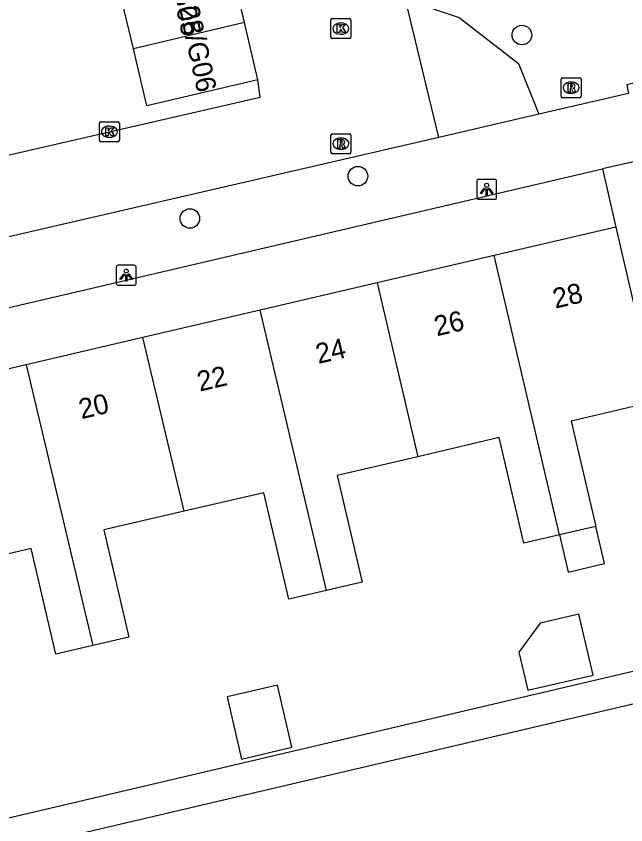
# Model space of a CAD drawing. Extents: x 158038 to 159242, y 380133 to 381214.
# Drawn here: x 158654.81 to 158685.28, y 380891.42 to 380931.84 of the extents above; entities that cross this region are included whole.
import ezdxf

# ---------------------------------------------------------------- set-up
doc = ezdxf.new("R2010")
doc.units = 0
for name, color, linetype in [('IMGEO_Boom', 7, 'Continuous'), ('IMGEO_Groenvoorziening', 7, 'Continuous'), ('IMGEO_Kolk', 7, 'Continuous'), ('IMGEO_Lichtpunt', 7, 'Continuous'), ('IMGEO_Pand', 7, 'Continuous'), ('IMGEO_Pand_nummerreeks', 7, 'Continuous'), ('IMGEO_Rijbaan_lokaal_open', 7, 'Continuous'), ('IMGEO_Rioolput', 7, 'Continuous'), ('IMGEO_Voetpad_open', 7, 'Continuous')]:
    doc.layers.add(name, color=color, linetype=linetype)

msp = doc.modelspace()

# ---------------------------------------------------------------- linework, layer by layer
at = {"layer": 'IMGEO_Boom'}
for centre in [(158680.085, 380930.895), (158671.888, 380923.84), (158663.489, 380921.724)]:
    msp.add_circle(centre, 0.489, dxfattribs=at)
at = {"layer": 'IMGEO_Groenvoorziening'}
for points in [[(158674.266, 380932.695), (158676.956, 380931.767), (158679.919, 380929.472), (158680.934, 380926.931)], [(158684.109, 380924.199), (158684.772, 380921.288)]]:
    msp.add_lwpolyline(points, dxfattribs=at)
at = {"layer": 'IMGEO_Kolk'}
for p, q in [((158670.533, 380930.79), (158670.533, 380931.642)), ((158670.608, 380931.716), (158671.46, 380931.716)), ((158671.021, 380931.496), (158671.046, 380931.496)), ((158671.534, 380931.642), (158671.534, 380930.79)), ((158671.46, 380930.716), (158670.608, 380930.716)), ((158671.044, 380930.936), (158671.019, 380930.936)), ((158659.041, 380926.561), (158659.893, 380926.561)), ((158658.966, 380925.635), (158658.966, 380926.487)), ((158659.454, 380926.341), (158659.479, 380926.341)), ((158659.967, 380926.487), (158659.967, 380925.635)), ((158659.477, 380925.781), (158659.452, 380925.781)), ((158659.893, 380925.561), (158659.041, 380925.561))]:
    msp.add_line(p, q, dxfattribs=at)
for points in [[(158670.533, 380930.79), (158670.533, 380931.642)], [(158670.608, 380931.716), (158671.46, 380931.716)], [(158670.854, 380931.416), (158670.977, 380931.416), (158670.977, 380931.265), (158671.107, 380931.416), (158671.271, 380931.416), (158671.125, 380931.265), (158671.278, 380931.016), (158671.126, 380931.016), (158671.041, 380931.18), (158670.977, 380931.113), (158670.977, 380931.016), (158670.854, 380931.016), (158670.854, 380931.416)], [(158671.534, 380931.642), (158671.534, 380930.79)], [(158671.46, 380930.716), (158670.608, 380930.716)], [(158659.041, 380926.561), (158659.893, 380926.561)], [(158658.966, 380925.635), (158658.966, 380926.487)], [(158659.287, 380926.261), (158659.41, 380926.261), (158659.41, 380926.11), (158659.54, 380926.261), (158659.704, 380926.261), (158659.558, 380926.11), (158659.711, 380925.861), (158659.559, 380925.861), (158659.474, 380926.025), (158659.41, 380925.958), (158659.41, 380925.861), (158659.287, 380925.861), (158659.287, 380926.261)], [(158659.967, 380926.487), (158659.967, 380925.635)], [(158659.893, 380925.561), (158659.041, 380925.561)]]:
    msp.add_lwpolyline(points, dxfattribs=at)
for centre, start, end in [((158670.61, 380931.64), 91.552, 178.448), ((158670.61, 380931.64), 91.552, 178.448), ((158671.458, 380931.64), 1.552, 88.448), ((158671.458, 380931.64), 1.552, 88.448), ((158670.61, 380930.792), 181.552, 268.448), ((158670.61, 380930.792), 181.552, 268.448), ((158671.458, 380930.792), 271.552, 358.448), ((158671.458, 380930.792), 271.552, 358.448), ((158659.043, 380926.485), 91.552, 178.448), ((158659.043, 380926.485), 91.552, 178.448), ((158659.891, 380926.485), 1.552, 88.448), ((158659.891, 380926.485), 1.552, 88.448), ((158659.043, 380925.637), 181.552, 268.448), ((158659.043, 380925.637), 181.552, 268.448), ((158659.891, 380925.637), 271.552, 358.448), ((158659.891, 380925.637), 271.552, 358.448)]:
    msp.add_arc(centre, 0.0765, start, end, dxfattribs=at)
for centre, major_axis, ratio, start_param, end_param in [((158671.02, 380931.216), (-0.387, 0.002), 0.722429, 4.712389, 7.853982), ((158671.045, 380931.216), (-0.39, 0.002), 0.717154, 1.570796, 4.712389), ((158659.453, 380926.061), (-0.387, 0.002), 0.722429, 4.712389, 7.853982), ((158659.478, 380926.061), (-0.39, 0.002), 0.717154, 1.570796, 4.712389)]:
    msp.add_ellipse(centre, major_axis=major_axis, ratio=ratio, start_param=start_param, end_param=end_param, dxfattribs=at)
at = {"layer": 'IMGEO_Lichtpunt'}
for p, q in [((158677.826, 380923.585), (158677.826, 380922.778)), ((158677.826, 380923.585), (158677.826, 380922.778)), ((158678.728, 380923.68), (158677.92, 380923.68)), ((158678.728, 380923.68), (158677.92, 380923.68)), ((158678.822, 380922.778), (158678.822, 380923.585)), ((158678.822, 380922.778), (158678.822, 380923.585)), ((158677.92, 380922.684), (158678.728, 380922.684)), ((158677.92, 380922.684), (158678.728, 380922.684)), ((158659.808, 380919.295), (158659.808, 380918.488)), ((158659.808, 380919.295), (158659.808, 380918.488)), ((158660.71, 380919.39), (158659.902, 380919.39)), ((158660.71, 380919.39), (158659.902, 380919.39)), ((158660.804, 380918.488), (158660.804, 380919.295)), ((158660.804, 380918.488), (158660.804, 380919.295)), ((158659.902, 380918.394), (158660.71, 380918.394)), ((158659.902, 380918.394), (158660.71, 380918.394))]:
    msp.add_line(p, q, dxfattribs=at)
for points in [[(158678.2, 380923.249), (158678.239, 380923.221), (158678.051, 380922.959), (158678.013, 380922.986), (158678.2, 380923.249)], [(158678.302, 380923.201), (158678.349, 380923.201), (158678.349, 380922.879), (158678.302, 380922.879), (158678.302, 380923.201)], [(158678.412, 380923.221), (158678.45, 380923.248), (158678.637, 380922.986), (158678.598, 380922.958), (158678.412, 380923.221)], [(158660.182, 380918.959), (158660.221, 380918.931), (158660.033, 380918.669), (158659.995, 380918.696), (158660.182, 380918.959)], [(158660.284, 380918.911), (158660.331, 380918.911), (158660.331, 380918.589), (158660.284, 380918.589), (158660.284, 380918.911)], [(158660.394, 380918.931), (158660.432, 380918.958), (158660.619, 380918.696), (158660.58, 380918.668), (158660.394, 380918.931)]]:
    msp.add_lwpolyline(points, dxfattribs=at)
for centre in [(158678.325, 380923.383), (158660.307, 380919.093)]:
    msp.add_circle(centre, 0.0994, dxfattribs=at)
for centre, start, end in [((158677.92, 380923.585), 90, 180), ((158677.92, 380923.585), 90, 180), ((158678.728, 380923.585), 0, 90), ((158678.728, 380923.585), 0, 90), ((158677.92, 380922.778), 180, 270), ((158677.92, 380922.778), 180, 270), ((158678.728, 380922.778), 270, 0), ((158678.728, 380922.778), 270, 360), ((158659.902, 380919.295), 90, 180), ((158659.902, 380919.295), 90, 180), ((158660.71, 380919.295), 0, 90), ((158660.71, 380919.295), 0, 90), ((158659.902, 380918.488), 180, 270), ((158659.902, 380918.488), 180, 270), ((158660.71, 380918.488), 270, 0), ((158660.71, 380918.488), 270, 360)]:
    msp.add_arc(centre, 0.0946, start, end, dxfattribs=at)
at = {"layer": 'IMGEO_Pand'}
for points in [[(158666.218, 380931.513), (158665.546, 380934.366)], [(158660.663, 380930.206), (158659.991, 380933.058)], [(158666.218, 380931.513), (158660.663, 380930.206)], [(158666.889, 380928.661), (158666.218, 380931.513)], [(158666.889, 380928.661), (158661.334, 380927.354), (158660.663, 380930.206)], [(158684.772, 380921.288), (158678.701, 380919.872)], [(158684.772, 380921.288), (158686.8, 380912.592)], [(158678.701, 380919.872), (158672.845, 380918.506)], [(158681.969, 380905.911), (158678.701, 380919.872)], [(158672.845, 380918.506), (158667, 380917.143)], [(158672.845, 380918.506), (158674.882, 380909.821)], [(158667, 380917.143), (158661.145, 380915.777)], [(158670.312, 380903.139), (158667, 380917.143)], [(158661.145, 380915.777), (158655.3, 380914.414)], [(158663.205, 380907.093), (158661.145, 380915.777)], [(158655.3, 380914.414), (158649.241, 380913.001)], [(158655.3, 380914.414), (158658.634, 380900.384)], [(158686.8, 380912.592), (158682.546, 380911.6), (158683.775, 380906.332)], [(158681.969, 380905.911), (158680.186, 380905.495), (158678.956, 380910.771), (158674.882, 380909.821)], [(158674.882, 380909.821), (158670.853, 380908.882), (158672.095, 380903.555), (158670.312, 380903.139)], [(158670.312, 380903.139), (158668.431, 380902.7), (158667.19, 380908.022), (158663.205, 380907.093)], [(158663.205, 380907.093), (158659.196, 380906.158), (158660.444, 380900.806), (158658.634, 380900.384)], [(158683.775, 380906.332), (158681.969, 380905.911)], [(158681.969, 380905.911), (158682.403, 380904.056), (158684.208, 380904.477), (158683.775, 380906.332)], [(158658.634, 380900.384), (158656.788, 380899.953), (158655.558, 380905.23), (158651.286, 380904.234)], [(158679.938, 380900.042), (158680.38, 380898.148), (158683.639, 380898.909), (158682.929, 380901.95), (158680.996, 380901.499), (158679.938, 380900.042)], [(158665.347, 380897.819), (158666.072, 380894.709), (158668.59, 380895.297), (158667.865, 380898.406), (158665.347, 380897.819)]]:
    msp.add_lwpolyline(points, dxfattribs=at)
at = {"layer": 'IMGEO_Rijbaan_lokaal_open'}
for points in [[(158675.929, 380925.769), (158674.266, 380932.695)], [(158638.865, 380921.332), (158667.001, 380927.792), (158666.889, 380928.661)], [(158675.929, 380925.769), (158636.891, 380916.763), (158636.843, 380917.154), (158619.873, 380913.305), (158620.128, 380912.212), (158625.512, 380888.677), (158633.627, 380853.786), (158633.666, 380853.62)]]:
    msp.add_lwpolyline(points, dxfattribs=at)
at = {"layer": 'IMGEO_Rioolput'}
for p, q in [((158682.045, 380927.836), (158682.045, 380928.688)), ((158682.12, 380928.762), (158682.972, 380928.762)), ((158683.046, 380928.688), (158683.046, 380927.836)), ((158682.533, 380928.542), (158682.558, 380928.542)), ((158682.972, 380927.762), (158682.12, 380927.762)), ((158682.556, 380927.982), (158682.531, 380927.982)), ((158670.537, 380925.038), (158670.537, 380925.89)), ((158670.612, 380925.964), (158671.464, 380925.964)), ((158671.025, 380925.744), (158671.05, 380925.744)), ((158671.538, 380925.89), (158671.538, 380925.038)), ((158671.464, 380924.964), (158670.612, 380924.964)), ((158671.048, 380925.184), (158671.023, 380925.184))]:
    msp.add_line(p, q, dxfattribs=at)
for points in [[(158682.045, 380927.836), (158682.045, 380928.688)], [(158682.12, 380928.762), (158682.972, 380928.762)], [(158683.046, 380928.688), (158683.046, 380927.836)], [(158682.634, 380928.46), (158682.382, 380928.462), (158682.382, 380928.062)], [(158682.382, 380928.062), (158682.506, 380928.062), (158682.506, 380928.224), (158682.517, 380928.224)], [(158682.56, 380928.381), (158682.506, 380928.381), (158682.506, 380928.3)], [(158682.506, 380928.3), (158682.558, 380928.3)], [(158682.564, 380928.195), (158682.635, 380928.062), (158682.775, 380928.062), (158682.71, 380928.188)], [(158682.972, 380927.762), (158682.12, 380927.762)], [(158670.537, 380925.038), (158670.537, 380925.89)], [(158670.612, 380925.964), (158671.464, 380925.964)], [(158671.538, 380925.89), (158671.538, 380925.038)], [(158671.126, 380925.662), (158670.874, 380925.664), (158670.874, 380925.264)], [(158670.874, 380925.264), (158670.998, 380925.264), (158670.998, 380925.426), (158671.009, 380925.426)], [(158671.052, 380925.583), (158670.998, 380925.583), (158670.998, 380925.502)], [(158670.998, 380925.502), (158671.05, 380925.502)], [(158671.056, 380925.397), (158671.127, 380925.264), (158671.267, 380925.264), (158671.202, 380925.39)], [(158671.464, 380924.964), (158670.612, 380924.964)]]:
    msp.add_lwpolyline(points, dxfattribs=at)
for centre, radius, start, end in [((158682.122, 380928.686), 0.0765, 91.552, 178.448), ((158682.122, 380928.686), 0.0765, 91.552, 178.448), ((158682.97, 380928.686), 0.0765, 1.552, 88.448), ((158682.97, 380928.686), 0.0765, 1.552, 88.448), ((158682.516, 380928.171), 0.0533, 26.0293, 88.6989), ((158682.542, 380928.489), 0.19, 274.7715, 282.9687), ((158682.566, 380928.285), 0.0964, 77.0061, 93.1865), ((158682.58, 380928.342), 0.0378, 276.6634, 79.6772), ((158682.633, 380928.35), 0.109, 350.3612, 89.416), ((158682.631, 380928.35), 0.112, 277.5842, 350.9817), ((158682.615, 380928.135), 0.108, 29.5134, 73.7905), ((158682.122, 380927.838), 0.0765, 181.552, 268.448), ((158682.122, 380927.838), 0.0765, 181.552, 268.448), ((158682.97, 380927.838), 0.0765, 271.552, 358.448), ((158682.97, 380927.838), 0.0765, 271.552, 358.448), ((158670.614, 380925.888), 0.0765, 91.552, 178.448), ((158670.614, 380925.888), 0.0765, 91.552, 178.448), ((158671.462, 380925.888), 0.0765, 1.552, 88.448), ((158671.462, 380925.888), 0.0765, 1.552, 88.448), ((158671.008, 380925.373), 0.0533, 26.0293, 88.6989), ((158671.034, 380925.691), 0.19, 274.7715, 282.9687), ((158671.058, 380925.487), 0.0964, 77.0061, 93.1865), ((158671.072, 380925.544), 0.0378, 276.6634, 79.6772), ((158671.125, 380925.552), 0.109, 350.3612, 89.416), ((158671.123, 380925.552), 0.112, 277.5842, 350.9817), ((158671.107, 380925.337), 0.108, 29.5134, 73.7905), ((158670.614, 380925.04), 0.0765, 181.552, 268.448), ((158670.614, 380925.04), 0.0765, 181.552, 268.448), ((158671.462, 380925.04), 0.0765, 271.552, 358.448), ((158671.462, 380925.04), 0.0765, 271.552, 358.448)]:
    msp.add_arc(centre, radius, start, end, dxfattribs=at)
for centre, major_axis, ratio, start_param, end_param in [((158682.532, 380928.262), (-0.387, 0.002), 0.722429, 4.712389, 7.853982), ((158682.557, 380928.262), (-0.39, 0.002), 0.717154, 1.570796, 4.712389), ((158671.024, 380925.464), (-0.387, 0.002), 0.722429, 4.712389, 7.853982), ((158671.049, 380925.464), (-0.39, 0.002), 0.717154, 1.570796, 4.712389)]:
    msp.add_ellipse(centre, major_axis=major_axis, ratio=ratio, start_param=start_param, end_param=end_param, dxfattribs=at)
at = {"layer": 'IMGEO_Voetpad_open'}
for points in [[(158689.258, 380929.353), (158685.323, 380928.413), (158685.421, 380927.973), (158680.934, 380926.931)], [(158680.934, 380926.931), (158675.929, 380925.769)], [(158686.026, 380924.634), (158684.109, 380924.199)], [(158649.241, 380913.001), (158648.527, 380915.901), (158684.109, 380924.199)], [(158651.286, 380904.234), (158654.284, 380891.736), (158689.742, 380900.062)], [(158690.107, 380898.509), (158654.656, 380890.185), (158656.751, 380881.537)]]:
    msp.add_lwpolyline(points, dxfattribs=at)

# ---------------------------------------------------------------- texts
at = {"layer": 'IMGEO_Pand_nummerreeks'}
for s, rotation, p in [('28/G05', 282.1886, (158662.182, 380935.064)), ('28/G06', 282.1886, (158662.941, 380932.258)), ('28', 13.1286, (158681.754, 380917.216)), ('26', 13.1286, (158675.829, 380915.834)), ('24', 13.1286, (158669.907, 380914.453)), ('22', 13.1286, (158663.982, 380913.071)), ('20', 13.1286, (158658.066, 380911.692))]:
    msp.add_text(s, height=1, rotation=rotation, dxfattribs=at).set_placement(p)

doc.saveas('drawing.dxf')
